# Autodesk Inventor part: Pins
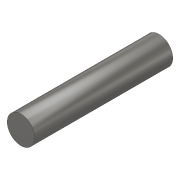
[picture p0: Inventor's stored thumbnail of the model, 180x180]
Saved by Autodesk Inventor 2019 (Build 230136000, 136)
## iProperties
Created: 2019-09
Part Number: Pins
Material: Steel, Alloy
Document SubType Name: Modeling
Designer: Admin
Density: 7.73 g/cm^3
Appearance: Semi-Polished
Author: Admin
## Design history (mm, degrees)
sketch "Sketch1"
  geometry: C1 r 5 at (0, 0); 1 further point
  constraints: 1 centre point, 1 coincident
  dimensions: "d0" = 10 diameter of C1
extrude "Extrusion1" new body sketch "Sketch1" stored distance "d1" = 50; taper "d2" = 0 deg
body "Solid1"
